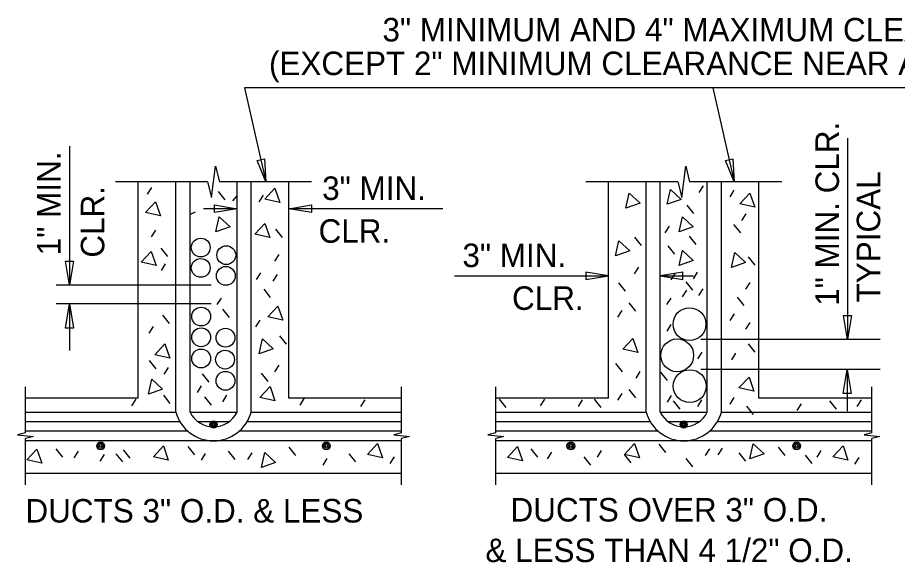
# Model space of a CAD drawing. Extents: x 0 to 22.7, y 0 to 15.7.
# Drawn here: x 15.98 to 19.878, y 4.662 to 7.075 of the extents above; entities that cross this region are included whole.
import ezdxf

# ---------------------------------------------------------------- set-up
doc = ezdxf.new("R2010")
doc.units = 0
for name, color, linetype in [('BRDG_ANNO_General-Notes', 7, 'Continuous'), ('BRDG_BASE_Obj-Line', 7, 'Continuous'), ('BRDG_BASE_Pattern', 7, 'Continuous'), ('BRDG_BASE_Rebar', 7, 'Continuous')]:
    doc.layers.add(name, color=color, linetype=linetype)

msp = doc.modelspace()

# ---------------------------------------------------------------- linework, layer by layer
at = {"layer": 'BRDG_ANNO_General-Notes'}
for p, q in [((21.1678, 6.7635), (16.9843, 6.7635)), ((16.9843, 6.7635), (17.0792, 6.348)), ((19.0592, 6.7635), (19.1542, 6.348)), ((19.6567, 6.5411), (19.6567, 5.6493)), ((16.2092, 6.5051), (16.2092, 5.8897)), ((17.0407, 6.4418), (17.0732, 6.4492)), ((17.0792, 6.348), (17.0407, 6.4418)), ((17.0732, 6.4492), (17.0792, 6.348)), ((19.1156, 6.4418), (19.1481, 6.4492)), ((19.1542, 6.348), (19.1156, 6.4418)), ((19.1481, 6.4492), (19.1542, 6.348)), ((16.8518, 6.212), (16.8518, 6.2453)), ((16.8518, 6.2453), (16.9518, 6.2286)), ((17.181, 6.2286), (17.281, 6.2453)), ((17.281, 6.2453), (17.281, 6.212)), ((16.9518, 6.2286), (16.8038, 6.2286)), ((16.9518, 6.2286), (16.8518, 6.212)), ((17.281, 6.212), (17.181, 6.2286)), ((17.864, 6.2286), (17.181, 6.2286)), ((16.1914, 5.9964), (16.227, 5.9964)), ((16.2092, 5.8897), (16.1914, 5.9964)), ((16.227, 5.9964), (16.2092, 5.8897)), ((17.9147, 5.9314), (18.5977, 5.9314)), ((18.4977, 5.948), (18.4977, 5.9147)), ((18.5977, 5.9314), (18.4977, 5.948)), ((18.4977, 5.9147), (18.5977, 5.9314)), ((18.9268, 5.948), (18.8268, 5.9314)), ((18.8268, 5.9314), (18.9749, 5.9314)), ((18.8268, 5.9314), (18.9268, 5.9147)), ((18.9268, 5.9147), (18.9268, 5.948)), ((16.8373, 5.8897), (16.1506, 5.8897)), ((16.8373, 5.8064), (16.1506, 5.8064)), ((16.1914, 5.6997), (16.2092, 5.8064)), ((16.2092, 5.8064), (16.2092, 5.601)), ((16.2092, 5.8064), (16.227, 5.6997)), ((19.639, 5.7559), (19.6745, 5.7559)), ((19.6567, 5.6493), (19.639, 5.7559)), ((19.6745, 5.7559), (19.6567, 5.6493)), ((16.227, 5.6997), (16.1914, 5.6997)), ((19.8005, 5.6493), (19.0068, 5.6493)), ((19.8011, 5.5166), (19.0068, 5.5166)), ((19.6376, 5.41), (19.6554, 5.5167)), ((19.6554, 5.5167), (19.6554, 5.3314)), ((19.6554, 5.5167), (19.6732, 5.41)), ((19.6732, 5.41), (19.6376, 5.41))]:
    msp.add_line(p, q, dxfattribs=at)
at = {"layer": 'BRDG_BASE_Obj-Line'}
for p, q in [((16.839, 6.2786), (16.8564, 6.4175)), ((16.8564, 6.4175), (16.8737, 6.348)), ((18.9223, 6.2786), (18.9397, 6.4175)), ((18.9397, 6.4175), (18.957, 6.348)), ((16.8216, 6.348), (16.4136, 6.348)), ((16.5143, 5.3897), (16.5143, 6.348)), ((16.8216, 6.348), (16.839, 6.2786)), ((17.2817, 6.348), (16.8737, 6.348)), ((17.181, 5.3897), (17.181, 6.348)), ((18.9049, 6.348), (18.497, 6.348)), ((18.5977, 5.3897), (18.5977, 6.348)), ((18.9049, 6.348), (18.9223, 6.2786)), ((19.365, 6.348), (18.957, 6.348)), ((19.2643, 5.3897), (19.2643, 6.348)), ((16.0143, 5.236), (16.0143, 5.4401)), ((17.681, 5.236), (17.681, 5.4401)), ((18.0977, 5.236), (18.0977, 5.4401)), ((19.7643, 5.236), (19.7643, 5.4401)), ((16.5143, 5.3897), (16.0143, 5.3897)), ((17.681, 5.3897), (17.181, 5.3897)), ((18.5977, 5.3897), (18.0977, 5.3897)), ((19.7643, 5.3897), (19.2643, 5.3897)), ((16.0143, 5.236), (15.9796, 5.2274)), ((15.9796, 5.2274), (16.0491, 5.2187)), ((17.681, 5.236), (17.6462, 5.2274)), ((17.6462, 5.2274), (17.7157, 5.2187)), ((18.0977, 5.236), (18.0629, 5.2274)), ((18.0629, 5.2274), (18.1324, 5.2187)), ((19.7643, 5.236), (19.7296, 5.2274)), ((19.7296, 5.2274), (19.7991, 5.2187)), ((16.0491, 5.2187), (16.0143, 5.21)), ((16.0143, 5.006), (16.0143, 5.21)), ((17.7157, 5.2187), (17.681, 5.21)), ((17.681, 5.006), (17.681, 5.21)), ((18.1324, 5.2187), (18.0977, 5.21)), ((18.0977, 5.006), (18.0977, 5.21)), ((19.7991, 5.2187), (19.7643, 5.21)), ((19.7643, 5.006), (19.7643, 5.21)), ((16.0143, 5.0564), (17.681, 5.0564)), ((18.0977, 5.0564), (19.7643, 5.0564))]:
    msp.add_line(p, q, dxfattribs=at)
for centre, radius in [((16.791, 6.0563), 0.0417), ((16.9041, 6.0228), 0.0417), ((16.791, 5.9662), 0.0417), ((16.9023, 5.9309), 0.0417), ((16.7928, 5.7507), 0.0417), ((18.9565, 5.717), 0.0729), ((16.7928, 5.6588), 0.0417), ((16.9006, 5.657), 0.0417), ((18.902, 5.579), 0.0729), ((16.7928, 5.5651), 0.0417), ((16.8988, 5.5598), 0.0417), ((16.9006, 5.4662), 0.0417), ((18.9577, 5.4424), 0.0729)]:
    msp.add_circle(centre, radius, dxfattribs=at)
at = {"layer": 'BRDG_BASE_Pattern'}
for p, q in [((16.5728, 6.323), (16.5542, 6.2934)), ((19.017, 6.33), (18.9984, 6.3005)), ((16.8678, 6.3048), (16.8973, 6.2679)), ((16.9334, 6.263), (16.9518, 6.2852)), ((17.067, 6.2885), (17.0484, 6.259)), ((19.1533, 6.3111), (19.1347, 6.2816)), ((18.9448, 6.2443), (18.9744, 6.2074)), ((16.7452, 6.2041), (16.7674, 6.2151)), ((19.2054, 6.2065), (19.1868, 6.1769)), ((16.5903, 6.134), (16.5717, 6.1044)), ((17.1223, 6.1375), (17.1518, 6.1006)), ((18.8665, 6.1515), (18.8479, 6.122)), ((19.1521, 6.158), (19.1817, 6.1211)), ((18.7124, 6.1024), (18.742, 6.0655)), ((18.9555, 6.1064), (18.985, 6.0695)), ((16.6147, 6.0534), (16.6443, 6.0166)), ((18.8599, 6.0639), (18.8895, 6.027)), ((17.1364, 6.0255), (17.1178, 5.9959)), ((19.2165, 6.0149), (19.246, 5.978)), ((16.6338, 5.9848), (16.6152, 5.9553)), ((18.73, 5.9695), (18.7114, 5.9399)), ((17.0559, 5.945), (17.0373, 5.9154)), ((17.129, 5.9369), (17.1104, 5.9073)), ((18.893, 5.9436), (18.8744, 5.9141)), ((18.9907, 5.9467), (18.9721, 5.9172)), ((18.6424, 5.8995), (18.672, 5.8626)), ((18.9395, 5.9048), (18.9691, 5.8679)), ((19.2234, 5.9016), (19.2048, 5.872)), ((17.0698, 5.8715), (17.0993, 5.8346)), ((18.943, 5.8672), (18.9244, 5.8376)), ((19.0148, 5.8739), (18.9962, 5.8443)), ((16.8808, 5.8329), (16.8622, 5.8034)), ((18.6879, 5.8119), (18.7174, 5.775)), ((18.8735, 5.8329), (18.8549, 5.8034)), ((19.1675, 5.8365), (19.197, 5.7996)), ((16.8878, 5.784), (16.9173, 5.7471)), ((18.6565, 5.777), (18.6379, 5.7474)), ((16.6211, 5.7565), (16.6507, 5.7196)), ((17.0523, 5.7349), (17.0337, 5.7054)), ((19.1541, 5.7633), (19.1355, 5.7339)), ((16.5798, 5.707), (16.5613, 5.6774)), ((18.8742, 5.7159), (18.8556, 5.6865)), ((19.2235, 5.7245), (19.2049, 5.6949)), ((17.1398, 5.6649), (17.1693, 5.628)), ((19.2165, 5.6299), (19.246, 5.593)), ((19.0108, 5.5936), (18.9922, 5.5641)), ((19.1606, 5.5879), (19.142, 5.5584)), ((16.5622, 5.5565), (16.5918, 5.5196)), ((17.1364, 5.5354), (17.1178, 5.5059)), ((18.6284, 5.5424), (18.658, 5.5055)), ((16.6463, 5.5249), (16.6277, 5.4954)), ((16.7968, 5.4969), (16.8263, 5.46)), ((17.0593, 5.5004), (17.0888, 5.4635)), ((18.737, 5.5074), (18.7184, 5.4779)), ((18.8274, 5.5045), (18.857, 5.4676)), ((16.7933, 5.4444), (16.7747, 5.4149)), ((18.6879, 5.4269), (18.7174, 5.39)), ((16.5028, 5.3849), (16.4842, 5.3554)), ((16.6253, 5.4024), (16.6548, 5.3655)), ((16.8072, 5.3954), (16.8368, 5.3585)), ((16.9054, 5.4024), (16.8868, 5.3729)), ((17.2484, 5.3884), (17.2298, 5.3589)), ((17.5179, 5.3815), (17.4993, 5.3519)), ((18.1139, 5.3849), (18.1434, 5.348)), ((18.3135, 5.3849), (18.2949, 5.3554)), ((18.4815, 5.3815), (18.4629, 5.3519)), ((18.5339, 5.3849), (18.5634, 5.348)), ((18.6565, 5.4094), (18.6379, 5.3799)), ((18.8756, 5.4003), (18.857, 5.3708)), ((19.01, 5.3815), (18.9914, 5.3519)), ((19.1535, 5.3919), (19.1349, 5.3624)), ((19.7171, 5.3815), (19.6985, 5.3519)), ((18.8835, 5.3774), (18.913, 5.3405)), ((19.2095, 5.3533), (19.239, 5.3165)), ((19.4511, 5.364), (19.4325, 5.3344)), ((19.577, 5.3779), (19.6066, 5.341)), ((18.8209, 5.1854), (18.8505, 5.1485)), ((16.1492, 5.1644), (16.1788, 5.1275)), ((16.2473, 5.1539), (16.2287, 5.1244)), ((16.4467, 5.1608), (16.4763, 5.124)), ((16.7338, 5.1749), (16.7633, 5.138)), ((16.9123, 5.1539), (16.9418, 5.117)), ((17.0173, 5.1469), (16.9988, 5.1174)), ((17.1818, 5.1714), (17.2113, 5.1345)), ((18.2539, 5.1644), (18.2834, 5.1275)), ((18.345, 5.1504), (18.3264, 5.1208)), ((18.5655, 5.1574), (18.5469, 5.1278)), ((19.0451, 5.1644), (19.0265, 5.1349)), ((19.101, 5.1679), (19.0824, 5.1383)), ((19.1745, 5.1469), (19.204, 5.11)), ((19.3495, 5.1714), (19.379, 5.1345)), ((19.5386, 5.1574), (19.52, 5.1278)), ((16.3628, 5.1399), (16.3442, 5.1103)), ((16.4152, 5.1433), (16.4447, 5.1065)), ((16.8108, 5.1434), (16.7922, 5.1139)), ((17.3499, 5.1224), (17.3313, 5.0928)), ((17.4478, 5.1433), (17.4773, 5.1065)), ((17.6474, 5.1294), (17.6288, 5.0999)), ((18.4884, 5.1294), (18.518, 5.0925)), ((18.6669, 5.1399), (18.6965, 5.103)), ((18.9399, 5.1224), (18.9695, 5.0855)), ((19.4685, 5.1364), (19.498, 5.0995)), ((19.7066, 5.1259), (19.688, 5.0964))]:
    msp.add_line(p, q, dxfattribs=at)
for points in [[(17.0745, 6.2709), (17.1189, 6.319), (17.1409, 6.2561)], [(18.6895, 6.2971), (18.7374, 6.2528), (18.6747, 6.2307)], [(18.8719, 6.3142), (18.9198, 6.27), (18.8571, 6.2479)], [(19.1794, 6.2499), (19.2237, 6.2979), (19.2457, 6.2352)], [(16.5459, 6.2114), (16.5903, 6.2594), (16.6123, 6.1967)], [(16.8728, 6.1919), (16.9208, 6.1477), (16.8581, 6.1256)], [(17.0304, 6.1152), (17.0747, 6.1632), (17.0968, 6.1005)], [(18.9251, 6.1923), (18.973, 6.1481), (18.9103, 6.126)], [(18.6439, 6.0862), (18.6919, 6.042), (18.6292, 6.0199)], [(18.9251, 6.0438), (18.973, 5.9996), (18.9103, 5.9775)], [(16.527, 5.9916), (16.5714, 6.0396), (16.5934, 5.9769)], [(19.1568, 6.0349), (19.2047, 5.9906), (19.142, 5.9685)], [(17.0885, 5.7494), (17.1329, 5.7974), (17.1549, 5.7346)], [(17.0643, 5.6522), (17.1122, 5.6079), (17.0495, 5.5858)], [(18.6611, 5.6058), (18.7055, 5.6539), (18.7276, 5.5911)], [(16.588, 5.5814), (16.6323, 5.6294), (16.6544, 5.5667)], [(16.5742, 5.4736), (16.6222, 5.4295), (16.5595, 5.4074)], [(19.1757, 5.4344), (19.2201, 5.4824), (19.2421, 5.4196)], [(17.0535, 5.3923), (17.0979, 5.4403), (17.1199, 5.3776)], [(17.5296, 5.1403), (17.574, 5.1883), (17.596, 5.1256)], [(18.6682, 5.1403), (18.7126, 5.1883), (18.7346, 5.1256)], [(19.239, 5.1867), (19.2869, 5.1424), (19.2242, 5.1203)], [(16.0209, 5.1158), (16.0653, 5.1639), (16.0873, 5.101)], [(16.581, 5.1298), (16.6254, 5.1778), (16.6474, 5.1151)], [(17.0747, 5.1481), (17.1227, 5.1039), (17.06, 5.0818)], [(18.1501, 5.1264), (18.1945, 5.1744), (18.2165, 5.1116)], [(19.5922, 5.1298), (19.6366, 5.1778), (19.6586, 5.1151)]]:
    msp.add_lwpolyline(points, close=True, dxfattribs=at)
at = {"layer": 'BRDG_BASE_Rebar'}
for p, q in [((16.681, 5.3272), (16.681, 6.348)), ((16.7435, 5.3272), (16.7435, 6.348)), ((16.9518, 5.3272), (16.9518, 6.348)), ((17.0143, 5.3272), (17.0143, 6.348)), ((18.7643, 5.3272), (18.7643, 6.348)), ((18.8268, 5.3272), (18.8268, 6.348)), ((19.0352, 5.3272), (19.0352, 6.348)), ((19.0977, 5.3272), (19.0977, 6.348)), ((16.0143, 5.3272), (16.681, 5.3272)), ((16.7435, 5.3272), (16.9518, 5.3272)), ((17.0143, 5.3272), (17.681, 5.3272)), ((18.0977, 5.3272), (18.7643, 5.3272)), ((18.8268, 5.3272), (19.0352, 5.3272)), ((19.0977, 5.3272), (19.7643, 5.3272)), ((16.0143, 5.2855), (16.6989, 5.2855)), ((16.7783, 5.2855), (16.9175, 5.2855)), ((16.9973, 5.2855), (17.681, 5.2855)), ((18.0977, 5.2855), (18.7822, 5.2855)), ((18.8617, 5.2855), (19.0008, 5.2855)), ((19.0806, 5.2855), (19.7643, 5.2855)), ((16.0143, 5.2439), (16.7324, 5.2439)), ((16.963, 5.2439), (17.681, 5.2439)), ((18.0977, 5.2439), (18.8157, 5.2439)), ((19.0463, 5.2439), (19.7643, 5.2439)), ((16.0143, 5.2022), (17.681, 5.2022)), ((18.0977, 5.2022), (19.7643, 5.2022))]:
    msp.add_line(p, q, dxfattribs=at)
for centre, radius in [((16.8476, 5.2723), 0.0156), ((16.8474, 5.2723), 0.0149), ((16.8474, 5.2723), 0.0149), ((16.8474, 5.2723), 0.0149), ((16.8472, 5.2724), 0.0141), ((16.8472, 5.2724), 0.0141), ((16.8472, 5.2724), 0.0141), ((16.8469, 5.2725), 0.0134), ((16.8476, 5.2723), 0.0104), ((16.8474, 5.2723), 0.00991), ((16.8474, 5.2723), 0.00991), ((16.8474, 5.2723), 0.00991), ((16.8472, 5.2724), 0.00941), ((16.8472, 5.2724), 0.00941), ((16.8472, 5.2724), 0.00941), ((16.8469, 5.2725), 0.00894), ((16.8476, 5.2723), 0.00522), ((16.8474, 5.2723), 0.00495), ((16.8474, 5.2723), 0.00495), ((16.8474, 5.2723), 0.00495), ((16.8472, 5.2724), 0.00471), ((16.8472, 5.2724), 0.00471), ((16.8472, 5.2724), 0.00471), ((16.8469, 5.2725), 0.00447), ((18.931, 5.2723), 0.0156), ((18.9307, 5.2723), 0.0149), ((18.9307, 5.2723), 0.0149), ((18.9307, 5.2723), 0.0149), ((18.9305, 5.2724), 0.0141), ((18.9305, 5.2724), 0.0141), ((18.9305, 5.2724), 0.0141), ((18.9302, 5.2725), 0.0134), ((18.931, 5.2723), 0.0104), ((18.9307, 5.2723), 0.00991), ((18.9307, 5.2723), 0.00991), ((18.9307, 5.2723), 0.00991), ((18.9305, 5.2724), 0.00941), ((18.9305, 5.2724), 0.00941), ((18.9305, 5.2724), 0.00941), ((18.9302, 5.2725), 0.00894), ((18.931, 5.2723), 0.00522), ((18.9307, 5.2723), 0.00495), ((18.9307, 5.2723), 0.00495), ((18.9307, 5.2723), 0.00495), ((18.9305, 5.2724), 0.00471), ((18.9305, 5.2724), 0.00471), ((18.9305, 5.2724), 0.00471), ((18.9302, 5.2725), 0.00447), ((16.3477, 5.1777), 0.0173), ((16.3477, 5.1777), 0.0116), ((17.3477, 5.1777), 0.0173), ((17.3477, 5.1777), 0.0116), ((18.431, 5.1777), 0.0173), ((18.431, 5.1777), 0.0116), ((19.431, 5.1777), 0.0173), ((19.431, 5.1777), 0.0116), ((16.3477, 5.1777), 0.00578), ((17.3477, 5.1777), 0.00578), ((18.431, 5.1777), 0.00578), ((19.431, 5.1777), 0.00578)]:
    msp.add_circle(centre, radius, dxfattribs=at)
for centre, radius, start, end in [((16.8477, 5.373), 0.1728, 195.3683, 344.6317), ((16.8477, 5.3788), 0.1163, 206.3608, 333.6392), ((18.931, 5.373), 0.1728, 195.3683, 344.6317), ((18.931, 5.3788), 0.1163, 206.3608, 333.6392)]:
    msp.add_arc(centre, radius, start, end, dxfattribs=at)

# ---------------------------------------------------------------- texts
at = {"layer": 'BRDG_ANNO_General-Notes'}
for s, height, p in [('3" MINIMUM AND 4" MAXIMUM CLEARANCE', 0.104115, (17.5961, 6.9694)), ('(EXCEPT 2" MINIMUM CLEARANCE NEAR ANCHORAGE)', 0.104115, (17.0935, 6.8203)), ('3" MIN.', 0.10413, (17.329, 6.2672)), ('CLR.', 0.10417, (17.3131, 6.0776)), ('3" MIN.', 0.10413, (17.9504, 5.9699)), ('CLR.', 0.10417, (18.1703, 5.7803)), ('DUCTS 3" O.D. & LESS', 0.104167, (16.0144, 4.8383)), ('DUCTS OVER 3" O.D.', 0.104167, (18.1634, 4.8427)), ('& LESS THAN 4 1/2" O.D.', 0.104115, (18.0523, 4.6631))]:
    msp.add_text(s, height=height, dxfattribs=at).set_placement(p)
for s, height, p in [('1" MIN. CLR.', 0.104167, (19.6187, 5.7982)), ('1" MIN.', 0.10417, (16.1701, 6.0223)), ('TYPICAL', 0.10417, (19.8014, 5.8133)), ('CLR.', 0.10411, (16.3638, 6.0118))]:
    msp.add_text(s, height=height, rotation=90, dxfattribs=at).set_placement(p)

doc.saveas('drawing.dxf')
